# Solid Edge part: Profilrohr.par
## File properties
Username: bmolnar
Dokumentum tartalom típus: 0
Author: bmolnar
Last saved by: bmolnar
Revision: 93
Sűrűség: 0,000 kg/m^3
Pontosság: 0,990
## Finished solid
Body 1: solid body, 59 faces, 170 edges, 112 vertices.
  Faces by surface: plane 30, cylinder 29
  Edges by curve: line 112, circle 58
Bounding box of the edges (mm): 40.000 x 264.000 x 40.000, from (-20, -9.5, -20) to (20, 254.5, 20).
Cylindrical faces by radius (mm): R0.2 x12, R0.5 x12, R5 x4, R12.5 x1
Planar faces by outward normal: +x 7, +y 1, +z 7, -x 7, -y 1, -z 7
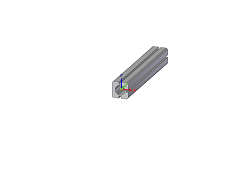
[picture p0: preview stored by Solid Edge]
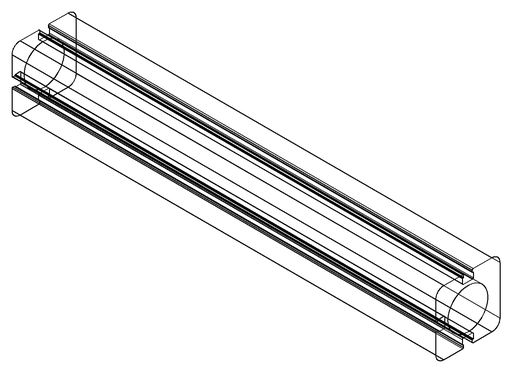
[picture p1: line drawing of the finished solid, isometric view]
